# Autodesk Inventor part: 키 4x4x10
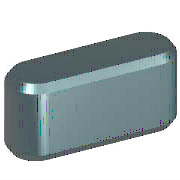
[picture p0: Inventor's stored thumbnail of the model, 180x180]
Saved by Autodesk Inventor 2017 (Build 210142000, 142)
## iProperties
IsCustomPart: 1
Created: 2012-02
Part Number: 키 4x4x10
Material: 강철, 연강
Description: 키 및 해당 키홈
Document SubType Name: Modeling
Standard: KS B 1311
Designer: test
Standards Organization: KS
Language: ko-KR
Size Designation: 4 x 4 x 10
Categories: <MemberInstance><Categories><Category DisplayName="샤프트 부품" InternalName="7f7aeb1f-a693-4053-b835-cee3144e0d98" Mnemonic="SHFT"><Category DisplayName="키" Interna
Density: 1 g/cm^3
Appearance: 노란색
Author: test
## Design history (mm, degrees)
workplane "Work Plane1"
workplane "Work Plane2"
sketch "스케치1"
  geometry: L1 (2, 2)-(8, 2); L2 (8, -2)-(2, -2); L3 (0, 9.4)-(0, -7.4) reference; L4 (-5, 0)-(30, 0) reference; L5 (10, 0)-(10, 7); A1 r 2 centre (2, 0) between (2, 2) and (2, -2); A2 r 2 centre (8, 0) between (8, -2) and (8, 2)
  constraints: 6 end point, 5 point on circle, 4 tangent, 3 point on line, 2 centre point, 1 horizontal, 1 parallel, 1 perpendicular
  dimensions: "d0" = 2 radius of A1 (= 0.5 x PB); "d13" = 2 radius of A2 (= 0.5 x PB); "d14" = 10 distance between parallel lines of L5 L3 (= NLG)
extrude "본체1" new body sketch "스케치1" taper "d3" = 0 deg; stored distance "d4" = 10
workplane "Work Plane3"
body "Solid1"
chamfer "모따기1" distance "d8" = 0.25 (= PHH); stored, may be unused: second distance "d9" = 0.25 (= PHH), angle "d15" = 45 deg
other parameters: "d1" = -2.5 (= -PNT), "d2" = 1.5 (= PH - PNT), "NLG" = 10 [user parameter; used in 3 equation terms], "PB" = 4 [user parameter; used in 2 equation terms], "PNT" = 2.5 [user parameter; used in 2 equation terms], "PH" = 4 [user parameter; used in 1 equation term], "PHH" = 0.25 [user parameter; used in 2 equation terms], "d10" = 0, "d16" = 0, "d17" = 0, "d18" = 0, "WDMAX" = 12 [user parameter], "RR" = 0.08 [user parameter], "PUEB" = 1.8 [user parameter]
